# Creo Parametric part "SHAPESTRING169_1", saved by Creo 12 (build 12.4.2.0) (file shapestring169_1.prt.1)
Units: Custom; MM, KILOGRAM, SECS

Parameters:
  PTC_WM_ITERATION = "0"
  PTC_WM_VERSION = "-.0"
  PTC_WM_LIFECYCLE_STATE = "In Work"
  PTC_WM_LIFECYCLE = "MO_CADDocument"
  PTC_WM_CREATED_BY = "Maximilian Roepper (Z0017RMS: MO)"
  PTC_WM_CREATED_ON = "18-Sep-26 11:36:42 AM"
  PTC_WM_MODIFIED_BY = "Maximilian Roepper (Z0017RMS: MO)"
  PTC_WM_MODIFIED_ON = "18-Sep-26 11:36:46 AM"
  PDMLINKNUMBER = "PDM000071455236"
  PTC_WM_NAME = "shapestring169_1.prt"
  PTC_WM_NUMBER = "PDM000071455236"

Other parameters: WEIGHT, WEIGHT_FACTOR, WEIGHT_ADD, _MASS_TEMP, _DIFF_TEMP, MC_ERRORS, SUPPLIER

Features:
  1. coordinate system
  2. datum plane "PRT_YZ"
  3. datum plane "PRT_XY"
  4. datum plane "PRT_XZ"
  5. coordinate system
  6. datum axis
  7. datum axis
  8. datum axis
  9. coordinate system
  10. imported feature
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
Other named items: PRT, SIEMENS_MO, DRW_VIEW_ORG, PRT_X, PRT_Y, PRT_Z, CS0, ROUGH_GROB

Layers: 00_STD_CSYS-KSYS, 01_STD_PLANES-EBENEN, 02_STD_AXES-ACHSEN, 03_STD_CSYS-KSYS, 24_IMPORT_FEAT-IMPORT_KE, INTFCLR

Surfaces: 1 plane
